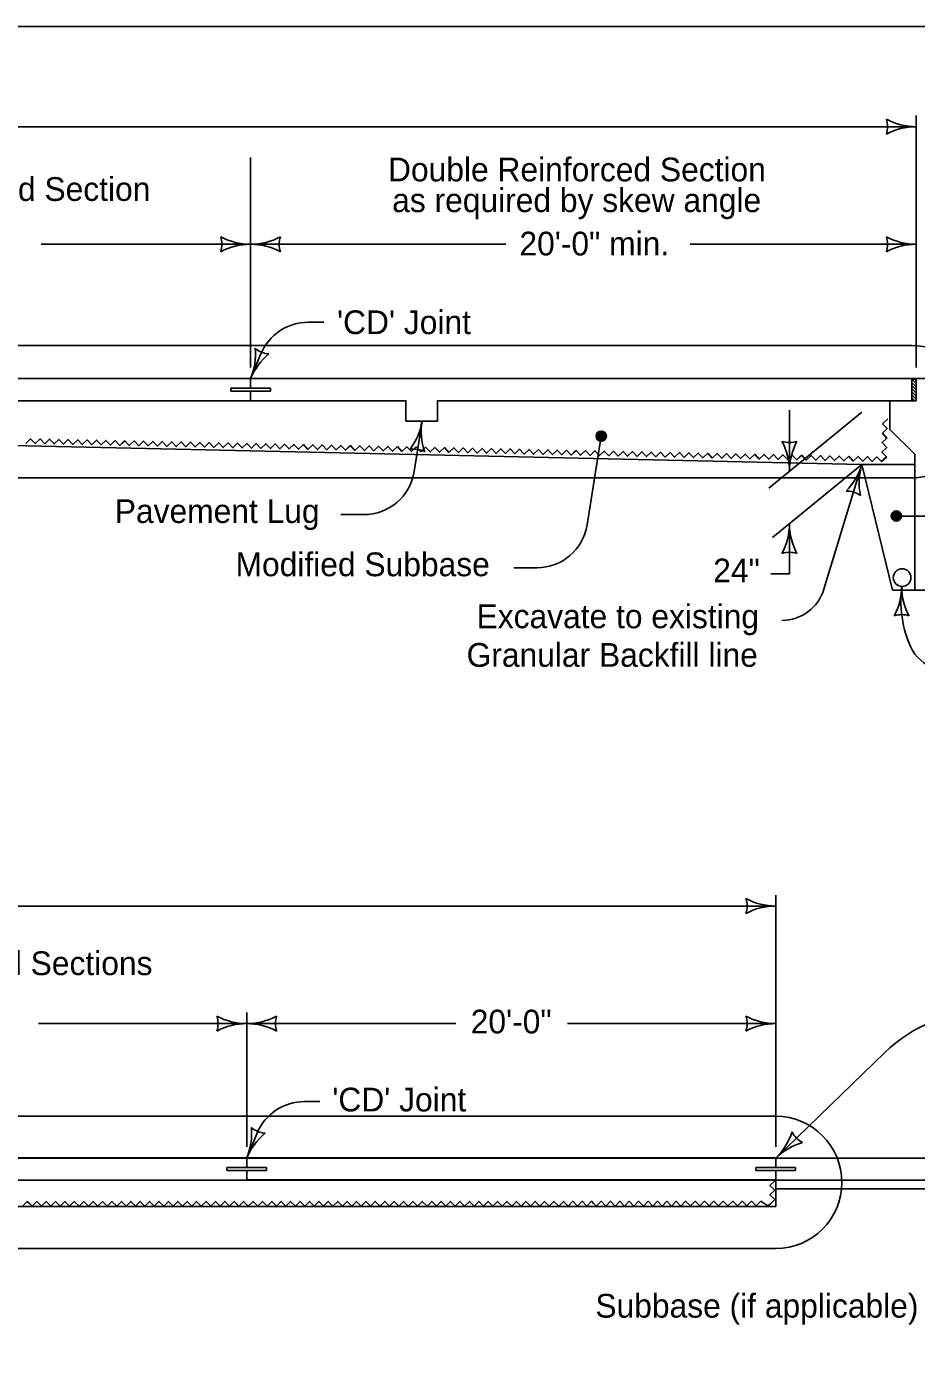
# Model space of a CAD drawing. Extents: x 10130 to 81668, y 5440 to 21644.
# Drawn here: x 15496 to 16095, y 9055 to 9944 of the extents above; entities that cross this region are included whole.
import ezdxf

# ---------------------------------------------------------------- set-up
doc = ezdxf.new("R2010")
doc.units = 0
for name, color, linetype in [('dsnNonPlotable', 7, 'Continuous'), ('dsnStdBlock', 7, 'Continuous'), ('dsnStdBlockModified', 7, 'Continuous'), ('dsnStdBlockNotModified', 7, 'Continuous'), ('dsnStdBorder', 7, 'Continuous'), ('SheetBorder', 7, 'Continuous')]:
    doc.layers.add(name, color=color, linetype=linetype)

msp = doc.modelspace()

# ---------------------------------------------------------------- linework, layer by layer
at = {"layer": 'dsnNonPlotable'}
for p, q in [((16095.04, 9714.12), (16095.04, 9883.89)), ((16092.07, 9876.46), (14220.97, 9876.46)), ((15646.57, 9714.12), (15646.57, 9855.76)), ((15646.57, 9797.26), (15505.41, 9797.26)), ((15818.61, 9797.26), (15646.57, 9797.26)), ((16092.07, 9797.26), (15942.68, 9797.26)), ((16058.43, 9684.07), (15995.64, 9632.94)), ((16009.62, 9644.32), (16009.62, 9685.51)), ((16058.43, 9648.78), (15998.16, 9599.7)), ((16009.62, 9575.13), (16009.62, 9609.03)), ((16009.62, 9575.13), (15997.18, 9575.13)), ((16000.4, 9189.06), (16000.4, 9358.82)), ((14129.3, 9351.39), (16000.4, 9351.39)), ((15644, 9189.06), (15644, 9279.62)), ((15503.67, 9272.19), (15644, 9272.19)), ((15644, 9272.19), (15784.79, 9272.19)), ((15860.07, 9272.19), (16000.4, 9272.19))]:
    msp.add_line(p, q, dxfattribs=at)
for centre, radius, start, end in [((16059.2, 9876.46), 16.51, 342.26665, 17.73335), ((16095.04, 9919.21), 42.75, 241.92751, 270), ((16095.04, 9833.71), 42.75, 90, 118.07249), ((15610.73, 9797.26), 16.51, 342.26665, 17.73335), ((15646.57, 9840.01), 42.75, 241.92751, 270), ((15646.57, 9840.01), 42.75, 270, 298.07249), ((15682.41, 9797.26), 16.51, 162.26665, 197.73335), ((16059.2, 9797.26), 16.51, 342.26665, 17.73335), ((16095.04, 9840.01), 42.75, 241.92751, 270), ((15646.57, 9754.51), 42.75, 90, 118.07249), ((15646.57, 9754.51), 42.75, 61.92751, 90), ((16095.04, 9754.51), 42.75, 90, 118.07249), ((16009.62, 9680.17), 16.51, 252.26665, 287.73335), ((15966.87, 9644.32), 42.75, 0, 28.07249), ((16052.36, 9644.32), 42.75, 151.92751, 180), ((15966.87, 9609.03), 42.75, 331.92751, 0), ((16052.36, 9609.03), 42.75, 180, 208.07249), ((16009.62, 9573.19), 16.51, 72.26665, 107.73335), ((15964.56, 9351.4), 16.51, 342.26665, 17.73335), ((16000.4, 9394.14), 42.75, 241.92751, 270), ((16000.4, 9308.65), 42.75, 90, 118.07249), ((15608.16, 9272.2), 16.51, 342.26665, 17.73335), ((15644, 9314.94), 42.75, 241.92751, 270), ((15608.16, 9272.2), 16.51, 342.26665, 17.73335), ((15644, 9314.94), 42.75, 241.92751, 270), ((15644, 9314.94), 42.75, 270, 298.07249), ((15679.85, 9272.2), 16.51, 162.26665, 197.73335), ((15964.56, 9272.2), 16.51, 342.26665, 17.73335), ((16000.4, 9314.94), 42.75, 241.92751, 270), ((15964.56, 9272.2), 16.51, 342.26665, 17.73335), ((16000.4, 9314.94), 42.75, 241.92751, 270), ((15644, 9229.45), 42.75, 90, 118.07249), ((15644, 9229.45), 42.75, 90, 118.07249), ((15644, 9229.45), 42.75, 61.92751, 90), ((16000.4, 9229.45), 42.75, 90, 118.07249), ((16000.4, 9229.45), 42.75, 90, 118.07249)]:
    msp.add_arc(centre, radius, start, end, dxfattribs=at)
at = {"layer": 'dsnStdBlock'}
for p, q in [((16095.04, 9703.33), (16092.07, 9706.3)), ((16095.04, 9701.23), (16092.07, 9704.2)), ((16095.04, 9705.42), (16094.17, 9706.3)), ((16095.04, 9699.12), (16092.07, 9702.09)), ((16095.04, 9697.02), (16092.07, 9699.99)), ((16095.04, 9694.92), (16092.07, 9697.89)), ((16095.04, 9692.82), (16092.07, 9695.79)), ((16095.04, 9691.75), (16077.22, 9691.75)), ((16094.02, 9691.75), (16092.07, 9693.7)), ((15997.06, 9166.79), (15995.15, 9166.79))]:
    msp.add_line(p, q, dxfattribs=at)
for points in [[(16073.27, 9652.35), (16075.01, 9654.01), (16071.92, 9657.25), (16075.16, 9660.34), (16072.06, 9663.58), (16075.3, 9666.67), (16072.21, 9669.92), (16075.45, 9673.01), (16072.36, 9676.25), (16075.6, 9679.34), (16075.45, 9679.5)], [(15560.16, 9663.31), (15558.54, 9661.77), (15555.44, 9665), (15552.21, 9661.9), (15549.11, 9665.13), (15545.88, 9662.04), (15542.78, 9665.27), (15539.54, 9662.17), (15536.44, 9665.4), (15533.2, 9662.31), (15530.11, 9665.54), (15526.87, 9662.44), (15523.77, 9665.68), (15520.54, 9662.58), (15517.43, 9665.82), (15514.2, 9662.71), (15511.1, 9665.95), (15507.87, 9662.85), (15504.77, 9666.09), (15501.53, 9662.99), (15498.43, 9666.22), (15495.2, 9663.12)], [(15636.18, 9661.69), (15634.56, 9660.14), (15631.46, 9663.38), (15628.22, 9660.27), (15625.12, 9663.51), (15621.89, 9660.41), (15618.79, 9663.65), (15615.56, 9660.55), (15612.46, 9663.78), (15609.22, 9660.68), (15606.12, 9663.92), (15602.88, 9660.82), (15599.79, 9664.05), (15596.55, 9660.95), (15593.45, 9664.18), (15590.22, 9661.09), (15587.12, 9664.32), (15583.88, 9661.22), (15580.78, 9664.46), (15577.55, 9661.36), (15574.45, 9664.6), (15571.21, 9661.49), (15568.12, 9664.73), (15564.88, 9661.63), (15561.78, 9664.87), (15560.16, 9663.31)], [(15712.19, 9660.06), (15710.57, 9658.51), (15707.48, 9661.75), (15704.24, 9658.65), (15701.14, 9661.88), (15697.9, 9658.78), (15694.8, 9662.02), (15691.57, 9658.92), (15688.47, 9662.16), (15685.24, 9659.05), (15682.14, 9662.29), (15678.9, 9659.19), (15675.8, 9662.43), (15672.56, 9659.33), (15669.47, 9662.56), (15666.23, 9659.46), (15663.13, 9662.7), (15659.9, 9659.6), (15656.79, 9662.83), (15653.56, 9659.73), (15650.46, 9662.97), (15647.23, 9659.87), (15644.13, 9663.1), (15640.89, 9660), (15637.8, 9663.24), (15636.18, 9661.69)], [(15788.2, 9658.43), (15786.59, 9656.89), (15783.49, 9660.12), (15780.25, 9657.02), (15777.16, 9660.26), (15773.92, 9657.16), (15770.82, 9660.39), (15767.58, 9657.29), (15764.48, 9660.53), (15761.25, 9657.43), (15758.15, 9660.66), (15754.92, 9657.56), (15751.82, 9660.8), (15748.58, 9657.7), (15745.48, 9660.94), (15742.24, 9657.83), (15739.15, 9661.07), (15735.91, 9657.97), (15732.81, 9661.21), (15729.58, 9658.11), (15726.48, 9661.34), (15723.24, 9658.24), (15720.14, 9661.48), (15716.91, 9658.38), (15713.81, 9661.61), (15712.19, 9660.06)], [(15864.22, 9656.81), (15862.6, 9655.26), (15859.5, 9658.5), (15856.27, 9655.39), (15853.17, 9658.63), (15849.93, 9655.53), (15846.84, 9658.77), (15843.6, 9655.67), (15840.5, 9658.9), (15837.26, 9655.8), (15834.16, 9659.04), (15830.93, 9655.94), (15827.83, 9659.17), (15824.6, 9656.08), (15821.5, 9659.31), (15818.26, 9656.21), (15815.16, 9659.44), (15811.92, 9656.34), (15808.83, 9659.58), (15805.59, 9656.48), (15802.49, 9659.72), (15799.26, 9656.61), (15796.16, 9659.85), (15792.92, 9656.75), (15789.82, 9659.99), (15788.2, 9658.43)], [(15940.24, 9655.18), (15938.62, 9653.64), (15935.52, 9656.87), (15932.28, 9653.77), (15929.18, 9657.01), (15925.95, 9653.9), (15922.85, 9657.14), (15919.61, 9654.04), (15916.52, 9657.28), (15913.28, 9654.17), (15910.18, 9657.41), (15906.94, 9654.31), (15903.84, 9657.55), (15900.61, 9654.45), (15897.51, 9657.68), (15894.28, 9654.58), (15891.18, 9657.82), (15887.94, 9654.72), (15884.84, 9657.95), (15881.6, 9654.86), (15878.51, 9658.09), (15875.27, 9654.99), (15872.17, 9658.22), (15868.94, 9655.12), (15865.84, 9658.36), (15864.22, 9656.81)], [(16016.25, 9653.56), (16014.63, 9652.01), (16011.53, 9655.24), (16008.3, 9652.14), (16005.2, 9655.38), (16001.97, 9652.28), (15998.86, 9655.51), (15995.63, 9652.42), (15992.53, 9655.65), (15989.29, 9652.55), (15986.2, 9655.79), (15982.96, 9652.68), (15979.86, 9655.92), (15976.62, 9652.82), (15973.52, 9656.06), (15970.29, 9652.95), (15967.19, 9656.19), (15963.96, 9653.09), (15960.86, 9656.33), (15957.62, 9653.23), (15954.52, 9656.46), (15951.28, 9653.36), (15948.19, 9656.6), (15944.95, 9653.5), (15941.85, 9656.73), (15940.24, 9655.18)], [(16074.88, 9653.89), (16074.88, 9653.89), (16071.64, 9650.79), (16068.54, 9654.02), (16065.31, 9650.93), (16062.21, 9654.16), (16058.97, 9651.06), (16055.87, 9654.3), (16052.64, 9651.2), (16049.54, 9654.43), (16046.3, 9651.33), (16043.2, 9654.57), (16039.97, 9651.47), (16036.87, 9654.7), (16033.64, 9651.6), (16030.54, 9654.84), (16027.3, 9651.74), (16024.2, 9654.97), (16020.97, 9651.87), (16017.87, 9655.11), (16016.25, 9653.56)], [(15996.77, 9150.78), (15999.67, 9153.68), (15996.5, 9156.85), (15999.67, 9160.02), (15996.5, 9163.18), (15999.67, 9166.35), (15999.24, 9166.79)], [(15497.76, 9150.73), (15499.34, 9149.14), (15502.51, 9152.32), (15505.68, 9149.15), (15508.85, 9152.32), (15512.01, 9149.15), (15515.18, 9152.32), (15518.35, 9149.15), (15521.52, 9152.32), (15524.69, 9149.15), (15527.85, 9152.32), (15531.02, 9149.15), (15534.19, 9152.32), (15537.36, 9149.16), (15540.53, 9152.33), (15543.69, 9149.16), (15546.86, 9152.33), (15550.03, 9149.16), (15553.2, 9152.33), (15556.37, 9149.16), (15559.53, 9152.34), (15562.7, 9149.17), (15565.87, 9152.34), (15569.04, 9149.17), (15572.21, 9152.34), (15573.79, 9150.75)], [(15573.79, 9150.75), (15575.37, 9149.17), (15578.54, 9152.34), (15581.71, 9149.18), (15584.88, 9152.34), (15588.05, 9149.18), (15591.21, 9152.34), (15594.38, 9149.18), (15597.55, 9152.35), (15600.72, 9149.18), (15603.89, 9152.35), (15607.05, 9149.18), (15610.22, 9152.35), (15613.39, 9149.19), (15616.56, 9152.35), (15619.73, 9149.19), (15622.89, 9152.36), (15626.06, 9149.19), (15629.23, 9152.36), (15632.4, 9149.19), (15635.57, 9152.36), (15638.73, 9149.2), (15641.9, 9152.37), (15645.07, 9149.2), (15648.24, 9152.37), (15649.82, 9150.78)], [(15649.82, 9150.78), (15651.41, 9149.2), (15654.57, 9152.37), (15657.74, 9149.2), (15660.91, 9152.37), (15664.08, 9149.2), (15667.25, 9152.37), (15670.41, 9149.21), (15673.58, 9152.37), (15676.75, 9149.21), (15679.92, 9152.38), (15683.09, 9149.21), (15686.25, 9152.38), (15689.42, 9149.21), (15692.59, 9152.38), (15695.76, 9149.22), (15698.93, 9152.39), (15702.09, 9149.22), (15705.26, 9152.39), (15708.43, 9149.22), (15711.6, 9152.39), (15714.77, 9149.23), (15717.93, 9152.39), (15721.1, 9149.23), (15724.27, 9152.39), (15725.85, 9150.81)], [(15725.85, 9150.81), (15727.44, 9149.23), (15730.61, 9152.4), (15733.77, 9149.23), (15736.94, 9152.4), (15740.11, 9149.23), (15743.28, 9152.4), (15746.45, 9149.23), (15749.61, 9152.4), (15752.78, 9149.24), (15755.95, 9152.41), (15759.12, 9149.24), (15762.29, 9152.41), (15765.45, 9149.24), (15768.62, 9152.41), (15771.79, 9149.25), (15774.96, 9152.41), (15778.13, 9149.25), (15781.29, 9152.41), (15784.46, 9149.25), (15787.63, 9152.42), (15790.8, 9149.25), (15793.97, 9152.42), (15797.13, 9149.25), (15800.3, 9152.42), (15801.89, 9150.84)], [(15801.89, 9150.84), (15803.47, 9149.25), (15806.64, 9152.43), (15809.81, 9149.26), (15812.97, 9152.43), (15816.14, 9149.26), (15819.31, 9152.43), (15822.48, 9149.26), (15825.65, 9152.43), (15828.81, 9149.27), (15831.98, 9152.43), (15835.15, 9149.27), (15838.32, 9152.43), (15841.49, 9149.27), (15844.65, 9152.44), (15847.82, 9149.27), (15850.99, 9152.44), (15854.16, 9149.27), (15857.33, 9152.44), (15860.49, 9149.27), (15863.66, 9152.45), (15866.83, 9149.28), (15870, 9152.45), (15873.17, 9149.28), (15876.33, 9152.45), (15877.92, 9150.87)], [(15877.92, 9150.87), (15879.5, 9149.28), (15882.67, 9152.46), (15885.84, 9149.29), (15889.01, 9152.46), (15892.17, 9149.29), (15895.34, 9152.46), (15898.51, 9149.29), (15901.68, 9152.46), (15904.85, 9149.29), (15908.01, 9152.46), (15911.18, 9149.29), (15914.35, 9152.46), (15917.52, 9149.3), (15920.69, 9152.47), (15923.85, 9149.3), (15927.02, 9152.47), (15930.19, 9149.3), (15933.36, 9152.47), (15936.53, 9149.3), (15939.69, 9152.48), (15942.86, 9149.31), (15946.03, 9152.48), (15949.2, 9149.31), (15952.37, 9152.48), (15953.95, 9150.89)], [(15953.95, 9150.89), (15955.53, 9149.31), (15958.7, 9152.48), (15961.87, 9149.32), (15965.04, 9152.48), (15968.21, 9149.32), (15971.37, 9152.48), (15974.54, 9149.32), (15977.71, 9152.49), (15980.88, 9149.32), (15984.05, 9152.49), (15987.21, 9149.32), (15990.38, 9152.49), (15994.94, 9149.33), (15996.77, 9150.78)], [(15493.01, 9149.14), (15496.17, 9152.31), (15497.76, 9150.73)]]:
    msp.add_lwpolyline(points, dxfattribs=at)
at = {"layer": 'dsnStdBlockModified'}
for p, q in [((15646.57, 9706.7), (15290.17, 9706.7)), ((16092.07, 9706.7), (15646.57, 9706.7)), ((15646.57, 9706.7), (15646.57, 9700.21)), ((15646.57, 9700.21), (15646.57, 9706.7)), ((16092.07, 9691.81), (16092.07, 9706.7)), ((15633.21, 9698.34), (15633.21, 9700.2)), ((15633.21, 9700.2), (15659.94, 9700.2)), ((15633.21, 9698.34), (15633.21, 9700.2)), ((15633.21, 9700.2), (15646.57, 9700.2)), ((15646.57, 9698.32), (15633.21, 9698.35)), ((15646.57, 9700.21), (15659.94, 9700.2)), ((15659.94, 9700.2), (15646.57, 9700.21)), ((15646.59, 9698.35), (15646.57, 9691.85)), ((15646.57, 9691.85), (15646.59, 9698.35)), ((15659.94, 9698.34), (15646.59, 9698.35)), ((15659.94, 9700.2), (15659.94, 9698.34)), ((15659.94, 9700.2), (15659.94, 9698.34)), ((15290.17, 9691.85), (15646.57, 9691.85)), ((16054.95, 9691.85), (16077.22, 9691.81)), ((16077.22, 9691.81), (16092.07, 9691.81)), ((16092.07, 9691.81), (16092.07, 9691.81)), ((15290.99, 9181.63), (15644, 9181.68)), ((15644, 9181.68), (15644, 9175.19)), ((15644, 9175.19), (15644, 9181.68)), ((15644, 9181.68), (16000.4, 9181.68)), ((16000.4, 9181.68), (16000.4, 9175.18)), ((15644, 9175.19), (15630.64, 9175.18)), ((15630.64, 9175.18), (15644, 9175.19)), ((15630.64, 9175.18), (15630.64, 9173.32)), ((15630.64, 9175.18), (15630.64, 9173.32)), ((15657.37, 9175.18), (15630.64, 9175.18)), ((15630.64, 9173.32), (15643.98, 9173.32)), ((15643.98, 9173.32), (15644, 9166.83)), ((15644, 9166.83), (15643.98, 9173.32)), ((15657.37, 9175.18), (15644, 9175.18)), ((15644, 9173.29), (15657.37, 9173.32)), ((15657.37, 9173.32), (15657.37, 9175.18)), ((15657.37, 9173.32), (15657.37, 9175.18)), ((16000.4, 9175.18), (15987.04, 9175.18)), ((15987.04, 9175.18), (15987.04, 9173.32)), ((15987.04, 9173.32), (16000.4, 9173.32)), ((16000.4, 9173.32), (16000.4, 9166.83)), ((15644, 9166.83), (15378.16, 9166.78)), ((16000.4, 9166.83), (15644, 9166.83))]:
    msp.add_line(p, q, dxfattribs=at)
msp.add_lwpolyline([(15646.57, 9691.85), (15751.23, 9691.85), (15751.23, 9678.1), (15772.47, 9678.1), (15772.47, 9691.85), (16054.95, 9691.85)], dxfattribs=at)
at = {"layer": 'dsnStdBlockNotModified'}
for p, q in [((15695.84, 9744.7), (15685.5, 9744.7)), ((16092.07, 9728.97), (15288.91, 9728.97)), ((15653.5, 9723.36), (15646.57, 9706.7)), ((15756.7, 9644.05), (15762.09, 9678.1)), ((15873.34, 9608.21), (15882.79, 9667.96)), ((16032.84, 9564.82), (16058.43, 9648.78)), ((16092.07, 9639.87), (15288.91, 9639.87)), ((15707.35, 9615.13), (15722.85, 9615.13)), ((16107.38, 9614.16), (16081.62, 9614.16)), ((15823.99, 9579.29), (15839.49, 9579.29)), ((16000.4, 9181.64), (16073.85, 9252.69)), ((15693.27, 9219.68), (15682.93, 9219.68)), ((15287.6, 9209.73), (16000.4, 9209.73)), ((15650.94, 9198.34), (15644, 9181.68)), ((15287.6, 9120.63), (16000.4, 9120.63))]:
    msp.add_line(p, q, dxfattribs=at)
for points in [[(15882.52, 9671.13), (15883.7, 9670.61), (15885.51, 9670.05), (15885.87, 9668.2), (15885.61, 9666.58), (15884.45, 9665.08), (15882.72, 9665.23), (15880.9, 9665.49), (15880.02, 9666.94), (15879.86, 9668.48), (15880.94, 9670.48), (15882.27, 9670.65), (15884.09, 9670.19), (15885.58, 9669.02), (15885.53, 9667.29), (15884.37, 9665.9), (15882.74, 9665.75), (15880.92, 9666.1), (15880.64, 9667.13), (15880.27, 9668.36), (15881.12, 9669.87), (15882.45, 9669.83), (15883.97, 9669.58), (15885.07, 9668.73), (15884.51, 9667.22), (15883.36, 9666.34), (15881.83, 9666.28), (15881.45, 9667.11), (15880.97, 9668.03), (15881.72, 9669.24), (15882.85, 9669.51), (15883.85, 9668.97), (15883.92, 9667.85), (15883.39, 9667.05), (15882.36, 9666.77), (15881.86, 9667.19), (15881.57, 9667.82), (15882.11, 9668.72), (15882.83, 9668.9), (15883.53, 9668.47), (15883.41, 9667.86), (15882.89, 9667.47), (15882.18, 9667.5), (15882.19, 9668), (15882.81, 9668.29)], [(16081.89, 9610.98), (16080.71, 9611.51), (16078.9, 9612.07), (16078.54, 9613.92), (16078.8, 9615.54), (16079.96, 9617.03), (16081.69, 9616.88), (16083.51, 9616.62), (16084.39, 9615.17), (16084.55, 9613.64), (16083.47, 9611.63), (16082.14, 9611.47), (16080.32, 9611.93), (16078.82, 9613.09), (16078.88, 9614.82), (16080.04, 9616.21), (16081.67, 9616.37), (16083.49, 9616.02), (16083.77, 9614.99), (16084.14, 9613.75), (16083.29, 9612.25), (16081.96, 9612.29), (16080.44, 9612.53), (16079.34, 9613.38), (16079.9, 9614.89), (16081.05, 9615.78), (16082.57, 9615.83), (16082.95, 9615.01), (16083.44, 9614.08), (16082.69, 9612.88), (16081.56, 9612.6), (16080.56, 9613.14), (16080.49, 9614.27), (16081.02, 9615.06), (16082.05, 9615.34), (16082.55, 9614.92), (16082.84, 9614.3), (16082.3, 9613.4), (16081.58, 9613.22), (16080.88, 9613.64), (16081, 9614.25), (16081.52, 9614.64), (16082.23, 9614.62), (16082.22, 9614.11), (16081.6, 9613.83)]]:
    msp.add_lwpolyline(points, dxfattribs=at)
for centre in [(15882.79, 9667.96), (16081.61, 9614.16)]:
    msp.add_circle(centre, 3.47, dxfattribs=at)
for centre, radius, start, end in [((15685.49, 9710.05), 34.65, 90, 157.40929), ((15607.1, 9723.12), 42.75, 337.40819, 5.48068), ((15686.04, 9690.28), 42.75, 129.3357, 157.40819), ((15660.34, 9739.79), 16.51, 229.67484, 265.14154), ((16092.07, 9684.42), 44.55, 270, 90.00042), ((15719.87, 9684.78), 42.75, 322.93819, 351.01068), ((15804.31, 9671.42), 42.75, 171.01068, 199.08317), ((15756.49, 9642.7), 16.51, 63.27733, 98.74403), ((15722.85, 9649.4), 34.27, 270, 351.01067), ((16017.54, 9661.25), 42.75, 314.97624, 343.04873), ((16099.32, 9636.32), 42.75, 163.04873, 191.12122), ((16047.98, 9614.5), 16.51, 55.31538, 90.78208), ((15839.49, 9613.57), 34.27, 270, 351.01067), ((16004.43, 9573.48), 29.7, 270, 343.04653), ((16042.64, 9566.83), 42.5, 332.03546, 0.10795), ((16156.01, 9556.07), 71.28, 171.40854, 209.49079), ((16127.64, 9566.99), 42.5, 180.10795, 208.18044), ((16085.21, 9531.28), 16.42, 72.3746, 107.84131), ((16133.99, 9558.67), 54.97, 223.28015, 269.66753), ((16143.38, 9180.82), 100, 90, 134.0496), ((15682.93, 9185.03), 34.65, 90, 157.40929), ((16000.4, 9165.18), 44.55, 270, 90), ((15604.54, 9198.1), 42.75, 337.40819, 5.48068), ((15683.47, 9165.26), 42.75, 129.3357, 157.40819), ((15657.77, 9214.77), 16.51, 229.67484, 265.14154), ((15970.68, 9212.36), 42.75, 314.04979, 342.12228), ((16026.16, 9206.56), 16.51, 206.31644, 241.78314), ((16030.12, 9150.91), 42.75, 105.97731, 134.04979)]:
    msp.add_arc(centre, radius, start, end, dxfattribs=at)
at = {"layer": 'dsnStdBorder'}
for p, q in [((16092.07, 9706.7), (14937.16, 9706.7)), ((15646.57, 9706.7), (15646.57, 9700.2)), ((16092.07, 9706.7), (16092.07, 9691.75)), ((16092.07, 9706.7), (16095.04, 9706.7)), ((16092.07, 9706.3), (16095.04, 9706.3)), ((16123.26, 9706.7), (16095.04, 9706.7)), ((16095.04, 9706.7), (16095.04, 9691.75)), ((15659.94, 9700.2), (15633.21, 9700.2)), ((15633.21, 9700.2), (15633.21, 9698.34)), ((15659.94, 9700.2), (15633.21, 9700.2)), ((15633.21, 9700.2), (15633.21, 9698.35)), ((15659.94, 9698.35), (15633.21, 9698.35)), ((15659.94, 9698.34), (15633.21, 9698.34)), ((15646.57, 9691.85), (15646.57, 9698.32)), ((15659.94, 9700.2), (15659.94, 9698.34)), ((14950.85, 9691.85), (15751.23, 9691.85)), ((15772.47, 9691.85), (16092.07, 9691.85)), ((16054.95, 9691.85), (16078.2, 9691.81)), ((16077.22, 9691.81), (16077.22, 9672.54)), ((14941.2, 9674.03), (16058.43, 9648.78)), ((16077.22, 9672.54), (16094.02, 9655.74)), ((16094.02, 9655.74), (16094.02, 9564.14)), ((16079.12, 9564.14), (16058.43, 9648.78)), ((16058.43, 9648.78), (16094.02, 9648.78)), ((16094.02, 9564.14), (16079.12, 9564.14)), ((16094.02, 9564.14), (16149.99, 9564.14)), ((15290.98, 9181.64), (16000.4, 9181.64)), ((15644, 9181.68), (15644, 9175.18)), ((16000.4, 9181.64), (16000.4, 9175.14)), ((16000.4, 9181.64), (16146.58, 9181.64)), ((15630.64, 9175.18), (15657.37, 9175.18)), ((15630.64, 9175.18), (15630.64, 9173.32)), ((15630.64, 9175.18), (15657.37, 9175.18)), ((15630.64, 9173.33), (15657.37, 9173.33)), ((15630.64, 9173.32), (15657.37, 9173.32)), ((15644, 9166.83), (15644, 9173.29)), ((15657.37, 9175.18), (15657.37, 9173.32)), ((15657.37, 9175.18), (15657.37, 9173.33)), ((15987.03, 9173.28), (15987.03, 9175.14)), ((15987.03, 9175.14), (16013.76, 9175.14)), ((16013.76, 9173.28), (15987.03, 9173.28)), ((16000.4, 9173.28), (16000.4, 9166.79)), ((16013.76, 9175.14), (16013.76, 9173.28)), ((15289.98, 9166.79), (16000.4, 9166.79)), ((16000.4, 9166.79), (16000.4, 9148.97)), ((16000.4, 9166.79), (16146.58, 9166.79)), ((16146.58, 9160.85), (16000.4, 9160.85)), ((15295.02, 9148.97), (16000.4, 9148.97))]:
    msp.add_line(p, q, dxfattribs=at)
msp.add_lwpolyline([(15772.47, 9691.85), (15772.47, 9678.1), (15751.23, 9678.1), (15751.23, 9691.85)], dxfattribs=at)
msp.add_circle((16085.53, 9572.66), 5.94, dxfattribs=at)
at = {"layer": 'SheetBorder'}
msp.add_lwpolyline([(13732.52, 9944.02), (16867.53, 9944.02), (16867.53, 7924.02), (13732.52, 7924.02)], close=True, dxfattribs=at)

# ---------------------------------------------------------------- texts
at = {"layer": 'dsnNonPlotable'}
for s, p in [('Double Reinforced Section', (15739.18, 9839.62)), ('Single Reinforced Section', (15332.89, 9826.45)), ('as required by skew angle', (15741.98, 9818.91)), ('20\'-0" min.', (15827.71, 9789.7)), ('24"', (15958.27, 9569.47)), ('Non-Reinforced Sections', (15342.64, 9304.84)), ('20\'-0"', (15794.9, 9265.56))]:
    msp.add_text(s, height=16, dxfattribs=at).set_placement(p)
at = {"layer": 'dsnStdBlockNotModified'}
for s, p in [("'CD' Joint", (15704.83, 9736.71)), ('Pavement Lug', (15555.11, 9609.44)), ('Modified Subbase', (15636.47, 9573.6)), ('Excavate to existing', (15798.84, 9538.57)), ('Granular Backfill line', (15792.12, 9512.57)), ("'CD' Joint", (15701.64, 9213.01)), ('Subbase (if applicable)', (15878.87, 9074.09))]:
    msp.add_text(s, height=16, dxfattribs=at).set_placement(p)

doc.saveas('drawing.dxf')
